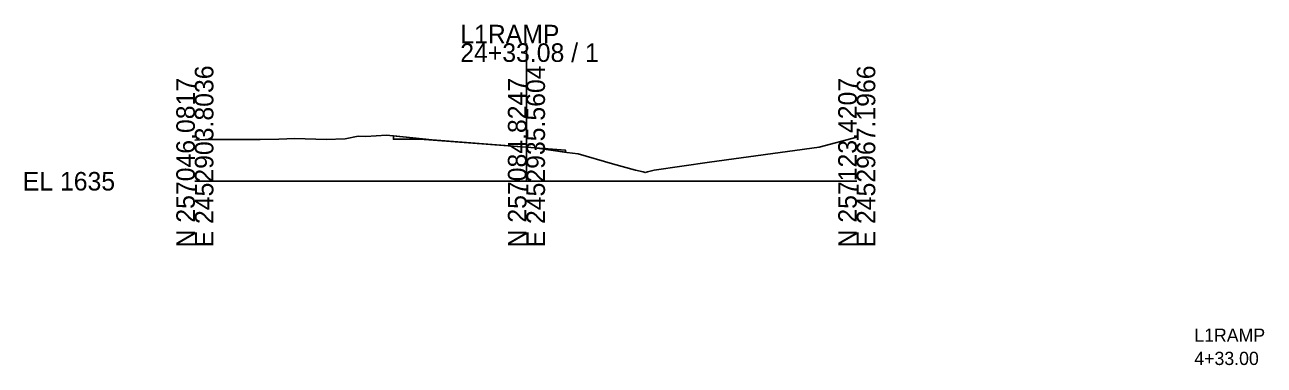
# Model space of a CAD drawing. Extents: x -26 to 438, y -10 to 6522.
# Drawn here: x -25.7 to 161.6, y 5972.2 to 6023.6 of the extents above; entities that cross this region are included whole.
import ezdxf

# ---------------------------------------------------------------- set-up
doc = ezdxf.new("R2010")
doc.units = 0
for name, color, linetype in [('DESIGN - EARTHWORK - Shapes', 7, 'Continuous'), ('DESIGN - SHEET - Light Grid', 7, 'Continuous'), ('DESIGN - TYPICAL - Warning Text', 7, 'Continuous'), ('SURVEY - GROUND - Top of Ground', 7, 'Continuous')]:
    doc.layers.add(name, color=color, linetype=linetype)

msp = doc.modelspace()

# ---------------------------------------------------------------- linework, layer by layer
at = {"layer": 'DESIGN - EARTHWORK - Shapes'}
for points in [[(35.86, 6006.27), (50.1, 6005.12), (50.12, 6005.12), (50, 6005.13), (34, 6006.33), (30, 6006.35), (30, 6006.84)], [(34, 6006.33), (50, 6005.13), (50.12, 6005.12), (50.1, 6005.12), (35.86, 6006.27), (30, 6006.84), (30, 6006.35)], [(34, 6006.33), (50, 6005.13), (50.12, 6005.12), (50.1, 6005.12), (35.86, 6006.27), (30, 6006.84), (30, 6006.35)], [(34, 6006.33), (50, 6005.13), (50.12, 6005.12), (50.1, 6005.12), (35.86, 6006.27), (30, 6006.84), (30, 6006.35)], [(34, 6006.33), (50, 6005.13), (50.12, 6005.12), (50.1, 6005.12), (35.86, 6006.27), (30, 6006.84), (30, 6006.35)], [(51.35, 6005.02), (56, 6004.37), (56, 6004.68), (50.12, 6005.12)], [(51.35, 6005.02), (56, 6004.37), (56, 6004.68), (50.12, 6005.12)], [(51.35, 6005.02), (56, 6004.37), (56, 6004.68), (50.12, 6005.12)], [(50.12, 6005.12), (51.35, 6005.02), (56, 6004.37), (56, 6004.68)], [(50.12, 6005.12), (51.35, 6005.02), (56, 6004.37), (56, 6004.68)]]:
    msp.add_lwpolyline(points, close=True, dxfattribs=at)
at = {"layer": 'DESIGN - SHEET - Light Grid'}
for p, q in [((50.1, 6000), (50.1, 6020.82)), ((0, 6000), (50.1, 6000)), ((50.1, 6000), (100, 6000))]:
    msp.add_line(p, q, dxfattribs=at)
at = {"layer": 'SURVEY - GROUND - Top of Ground'}
msp.add_lwpolyline([(0, 6006.2), (1.56, 6006.29), (9.88, 6006.31), (12.7, 6006.37), (15.11, 6006.43), (19.84, 6006.28), (22.69, 6006.4), (24.69, 6006.81), (25.83, 6006.78), (28.94, 6006.94), (35.86, 6006.27), (50.1, 6005.12), (51.35, 6005.02), (56.22, 6004.34), (57.89, 6004.12), (63.08, 6002.64), (66.56, 6001.68), (67.71, 6001.42), (68.03, 6001.31), (68.37, 6001.42), (69.4, 6001.66), (77.76, 6002.87), (94.3, 6005.16), (100, 6006.68)], dxfattribs=at)

# ---------------------------------------------------------------- texts
at = {"layer": 'DESIGN - SHEET - Light Grid'}
for s, p in [('L1RAMP', (40.1, 6020.82)), ('24+33.08 / 1', (40.1, 6018.02)), ('EL 1635', (-26, 5998.6))]:
    msp.add_text(s, height=2.8, dxfattribs=at).set_placement(p)
for s, p in [('E 2452903.8036', (2.8, 5990)), ('E 2452935.5604', (52.9, 5990)), ('E 2452967.1966', (102.8, 5990)), ('N 257046.0817', (0, 5990)), ('N 257084.8247', (50.1, 5990)), ('N 257123.4207', (100, 5990))]:
    msp.add_text(s, height=2.8, rotation=90, dxfattribs=at).set_placement(p)
at = {"layer": 'DESIGN - TYPICAL - Warning Text'}
for s, p in [('L1RAMP', (151, 5975.75)), ('4+33.00', (151, 5972.25))]:
    msp.add_text(s, height=2, dxfattribs=at).set_placement(p)

doc.saveas('drawing.dxf')
